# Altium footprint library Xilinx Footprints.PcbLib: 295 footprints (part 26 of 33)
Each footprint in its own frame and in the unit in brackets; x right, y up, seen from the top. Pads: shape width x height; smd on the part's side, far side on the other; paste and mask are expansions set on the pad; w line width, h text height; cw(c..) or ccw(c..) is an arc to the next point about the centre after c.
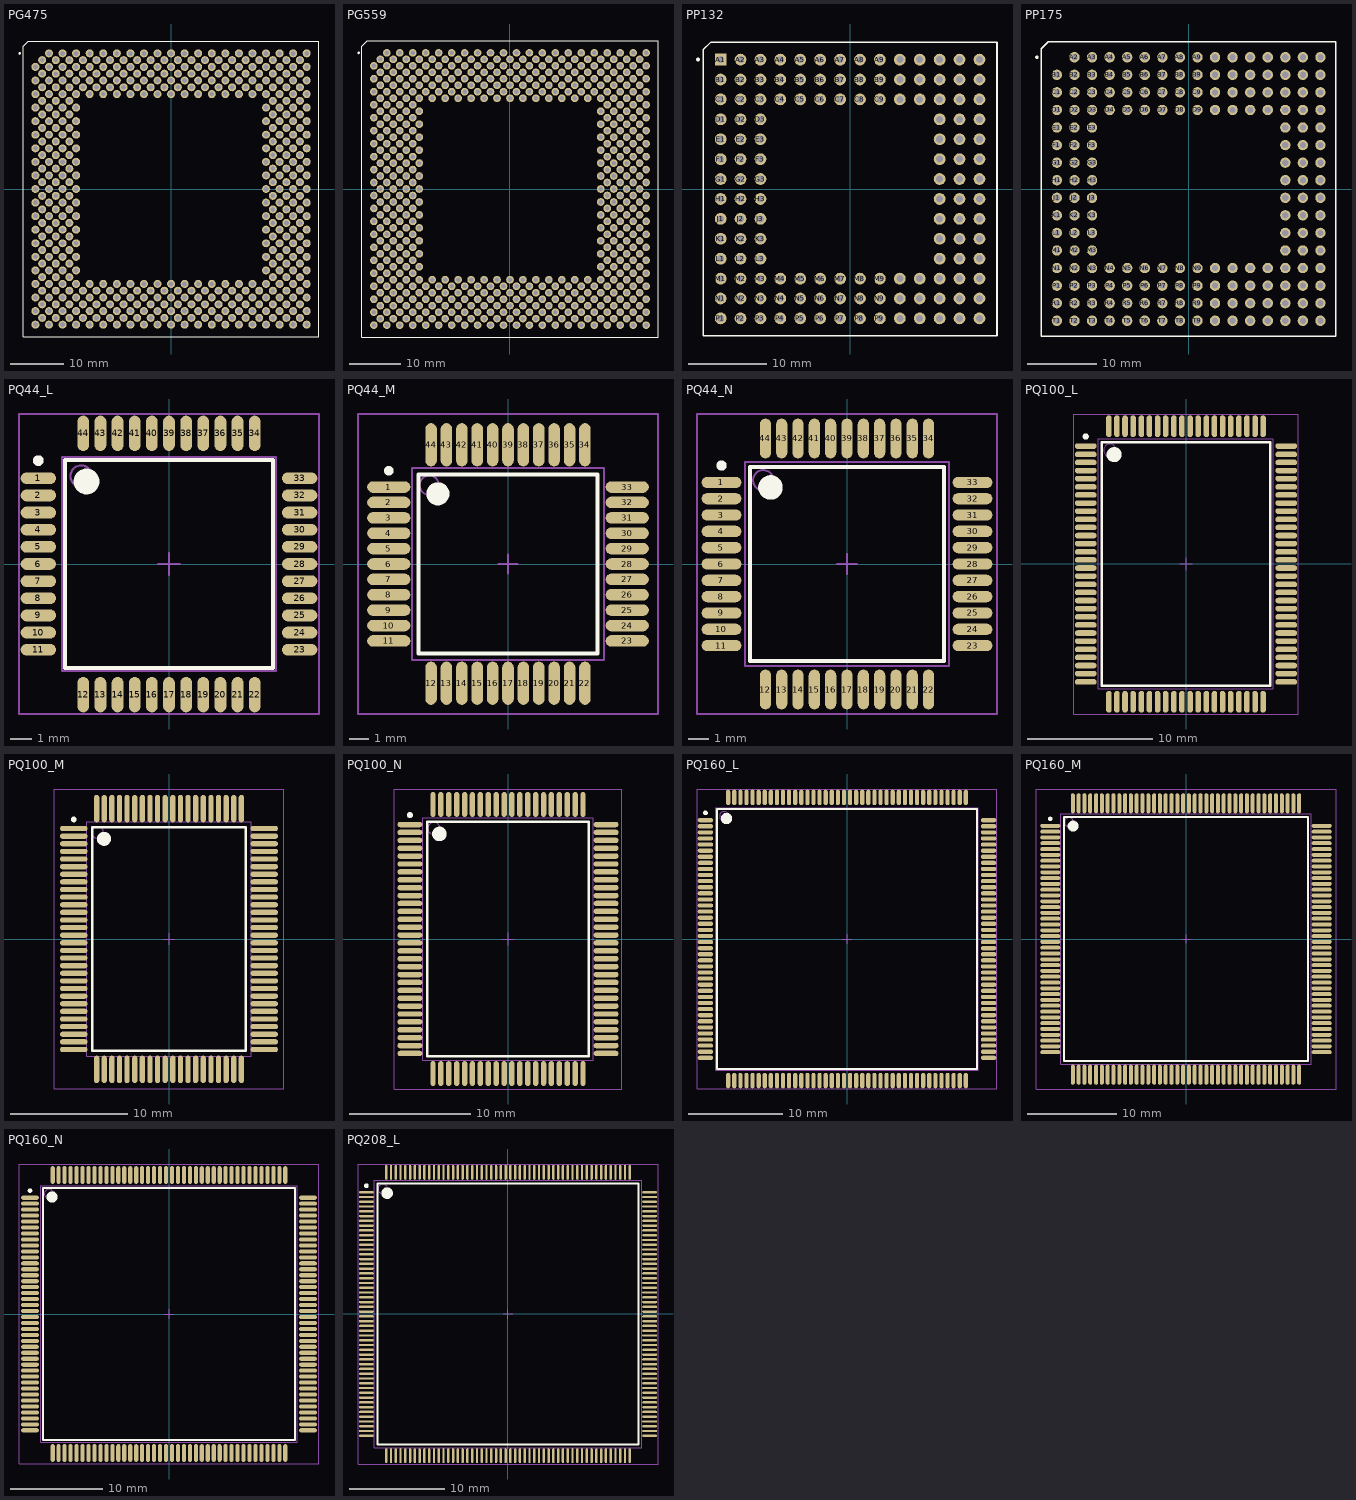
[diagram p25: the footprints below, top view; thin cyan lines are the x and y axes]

## PG475 [mm] "475-Pin Ceramic Pin Grid Array (PG475)"
height 5.86
pads (475):
  round 1.5 hole 0.9: A3(-22.86,25.4) A5(-20.32,25.4) A7(-17.78,25.4) A9(-15.24,25.4) A11(-12.7,25.4) A13(-10.16,25.4) A15(-7.62,25.4) A17(-5.08,25.4) A19(-2.54,25.4) A21(0,25.4) A23(2.54,25.4) A25(5.08,25.4) A27(7.62,25.4) A29(10.16,25.4) A31(12.7,25.4) A33(15.24,25.4) A35(17.78,25.4) A37(20.32,25.4) A39(22.86,25.4) A41(25.4,25.4) AA1(-25.4,0) AA3(-22.86,0) AA5(-20.32,0) AA7(-17.78,0) AA35(17.78,0) AA37(20.32,0) AA39(22.86,0) AA41(25.4,0) AB2(-24.13,-1.27) AB4(-21.59,-1.27) AB6(-19.05,-1.27) AB36(19.05,-1.27) AB38(21.59,-1.27) AB40(24.13,-1.27) AC1(-25.4,-2.54) AC3(-22.86,-2.54) AC5(-20.32,-2.54) AC7(-17.78,-2.54) AC35(17.78,-2.54) AC37(20.32,-2.54) AC39(22.86,-2.54) AC41(25.4,-2.54) AD2(-24.13,-3.81) AD4(-21.59,-3.81) AD6(-19.05,-3.81) AD36(19.05,-3.81) AD38(21.59,-3.81) AD40(24.13,-3.81) AE1(-25.4,-5.08) AE3(-22.86,-5.08) AE5(-20.32,-5.08) AE7(-17.78,-5.08) AE35(17.78,-5.08) AE37(20.32,-5.08) AE39(22.86,-5.08) AE41(25.4,-5.08) AF2(-24.13,-6.35) AF4(-21.59,-6.35) AF6(-19.05,-6.35) AF36(19.05,-6.35) AF38(21.59,-6.35) AF40(24.13,-6.35) AG1(-25.4,-7.62) AG3(-22.86,-7.62) AG5(-20.32,-7.62) AG7(-17.78,-7.62) AG35(17.78,-7.62) AG37(20.32,-7.62) AG39(22.86,-7.62) AG41(25.4,-7.62) AH2(-24.13,-8.89) AH4(-21.59,-8.89) AH6(-19.05,-8.89) AH36(19.05,-8.89) AH38(21.59,-8.89) AH40(24.13,-8.89) AJ1(-25.4,-10.16) AJ3(-22.86,-10.16) AJ5(-20.32,-10.16) AJ7(-17.78,-10.16) AJ35(17.78,-10.16) AJ37(20.32,-10.16) AJ39(22.86,-10.16) AJ41(25.4,-10.16) AK2(-24.13,-11.43) AK4(-21.59,-11.43) AK6(-19.05,-11.43) AK36(19.05,-11.43) AK38(21.59,-11.43) AK40(24.13,-11.43) AL1(-25.4,-12.7) AL3(-22.86,-12.7) AL5(-20.32,-12.7) AL7(-17.78,-12.7) AL35(17.78,-12.7) AL37(20.32,-12.7) AL39(22.86,-12.7) AL41(25.4,-12.7) AM2(-24.13,-13.97) AM4(-21.59,-13.97) AM6(-19.05,-13.97) AM36(19.05,-13.97) AM38(21.59,-13.97) AM40(24.13,-13.97) AN1(-25.4,-15.24) AN3(-22.86,-15.24) AN5(-20.32,-15.24) AN7(-17.78,-15.24) AN35(17.78,-15.24) AN37(20.32,-15.24) AN39(22.86,-15.24) AN41(25.4,-15.24) AP2(-24.13,-16.51) AP4(-21.59,-16.51) AP6(-19.05,-16.51) AP36(19.05,-16.51) AP38(21.59,-16.51) AP40(24.13,-16.51) AR1(-25.4,-17.78) AR3(-22.86,-17.78) AR5(-20.32,-17.78) AR7(-17.78,-17.78) AR9(-15.24,-17.78) AR11(-12.7,-17.78) AR13(-10.16,-17.78) AR15(-7.62,-17.78) AR17(-5.08,-17.78) AR19(-2.54,-17.78) AR21(0,-17.78) AR23(2.54,-17.78) AR25(5.08,-17.78) AR27(7.62,-17.78) AR29(10.16,-17.78) AR31(12.7,-17.78) AR33(15.24,-17.78) AR35(17.78,-17.78) AR37(20.32,-17.78) AR39(22.86,-17.78) AR41(25.4,-17.78) AT2(-24.13,-19.05) AT4(-21.59,-19.05) AT6(-19.05,-19.05) AT8(-16.51,-19.05) AT10(-13.97,-19.05) AT12(-11.43,-19.05) AT14(-8.89,-19.05) AT16(-6.35,-19.05) AT18(-3.81,-19.05) AT20(-1.27,-19.05) AT22(1.27,-19.05) AT24(3.81,-19.05) AT26(6.35,-19.05) AT28(8.89,-19.05) AT30(11.43,-19.05) AT32(13.97,-19.05) AT34(16.51,-19.05) AT36(19.05,-19.05) AT38(21.59,-19.05) AT40(24.13,-19.05) AU1(-25.4,-20.32) AU3(-22.86,-20.32) AU5(-20.32,-20.32) AU7(-17.78,-20.32) AU9(-15.24,-20.32) AU11(-12.7,-20.32) AU13(-10.16,-20.32) AU15(-7.62,-20.32) AU17(-5.08,-20.32) AU19(-2.54,-20.32) AU21(0,-20.32) AU23(2.54,-20.32) AU25(5.08,-20.32) AU27(7.62,-20.32) AU29(10.16,-20.32) AU31(12.7,-20.32) AU33(15.24,-20.32) AU35(17.78,-20.32) AU37(20.32,-20.32) AU39(22.86,-20.32) AU41(25.4,-20.32) AV2(-24.13,-21.59) AV4(-21.59,-21.59) AV6(-19.05,-21.59) AV8(-16.51,-21.59) AV10(-13.97,-21.59) AV12(-11.43,-21.59) AV14(-8.89,-21.59) AV16(-6.35,-21.59) AV18(-3.81,-21.59) AV20(-1.27,-21.59) AV22(1.27,-21.59) AV24(3.81,-21.59) AV26(6.35,-21.59) AV28(8.89,-21.59) AV30(11.43,-21.59) AV32(13.97,-21.59) AV34(16.51,-21.59) AV36(19.05,-21.59) AV38(21.59,-21.59) AV40(24.13,-21.59) AW1(-25.4,-22.86) AW3(-22.86,-22.86) AW5(-20.32,-22.86) AW7(-17.78,-22.86) AW9(-15.24,-22.86) AW11(-12.7,-22.86) AW13(-10.16,-22.86) AW15(-7.62,-22.86) AW17(-5.08,-22.86) AW19(-2.54,-22.86) AW21(0,-22.86) AW23(2.54,-22.86) AW25(5.08,-22.86) AW27(7.62,-22.86) AW29(10.16,-22.86) AW31(12.7,-22.86) AW33(15.24,-22.86) AW35(17.78,-22.86) AW37(20.32,-22.86) AW39(22.86,-22.86) AW41(25.4,-22.86) AY2(-24.13,-24.13) AY4(-21.59,-24.13) AY6(-19.05,-24.13) AY8(-16.51,-24.13) AY10(-13.97,-24.13) AY12(-11.43,-24.13) AY14(-8.89,-24.13) AY16(-6.35,-24.13) AY18(-3.81,-24.13) AY20(-1.27,-24.13) AY22(1.27,-24.13) AY24(3.81,-24.13) AY26(6.35,-24.13) AY28(8.89,-24.13) AY30(11.43,-24.13) AY32(13.97,-24.13) AY34(16.51,-24.13) AY36(19.05,-24.13) AY38(21.59,-24.13) AY40(24.13,-24.13) B2(-24.13,24.13) B4(-21.59,24.13) B6(-19.05,24.13) B8(-16.51,24.13) B10(-13.97,24.13) B12(-11.43,24.13) B14(-8.89,24.13) B16(-6.35,24.13) B18(-3.81,24.13) B20(-1.27,24.13) B22(1.27,24.13) B24(3.81,24.13) B26(6.35,24.13) B28(8.89,24.13) B30(11.43,24.13) B32(13.97,24.13) B34(16.51,24.13) B36(19.05,24.13) B38(21.59,24.13) B40(24.13,24.13) BA1(-25.4,-25.4) BA3(-22.86,-25.4) BA5(-20.32,-25.4) BA7(-17.78,-25.4) BA9(-15.24,-25.4) BA11(-12.7,-25.4) BA13(-10.16,-25.4) BA15(-7.62,-25.4) BA17(-5.08,-25.4) BA19(-2.54,-25.4) BA21(0,-25.4) BA23(2.54,-25.4) BA25(5.08,-25.4) BA27(7.62,-25.4) BA29(10.16,-25.4) BA31(12.7,-25.4) BA33(15.24,-25.4) BA35(17.78,-25.4) BA37(20.32,-25.4) BA39(22.86,-25.4) BA41(25.4,-25.4) C1(-25.4,22.86) C3(-22.86,22.86) C5(-20.32,22.86) C7(-17.78,22.86) C9(-15.24,22.86) C11(-12.7,22.86) C13(-10.16,22.86) C15(-7.62,22.86) C17(-5.08,22.86) C19(-2.54,22.86) C21(0,22.86) C23(2.54,22.86) C25(5.08,22.86) C27(7.62,22.86) C29(10.16,22.86) C31(12.7,22.86) C33(15.24,22.86) C35(17.78,22.86) C37(20.32,22.86) C39(22.86,22.86) C41(25.4,22.86) D2(-24.13,21.59) D4(-21.59,21.59) D6(-19.05,21.59) D8(-16.51,21.59) D10(-13.97,21.59) D12(-11.43,21.59) D14(-8.89,21.59) D16(-6.35,21.59) D18(-3.81,21.59) D20(-1.27,21.59) D22(1.27,21.59) D24(3.81,21.59) D26(6.35,21.59) D28(8.89,21.59) D30(11.43,21.59) D32(13.97,21.59) D34(16.51,21.59) D36(19.05,21.59) D38(21.59,21.59) D40(24.13,21.59) E1(-25.4,20.32) E3(-22.86,20.32) E5(-20.32,20.32) E7(-17.78,20.32) E9(-15.24,20.32) E11(-12.7,20.32) E13(-10.16,20.32) E15(-7.62,20.32) E17(-5.08,20.32) E19(-2.54,20.32) E21(0,20.32) E23(2.54,20.32) E25(5.08,20.32) E27(7.62,20.32) E29(10.16,20.32) E31(12.7,20.32) E33(15.24,20.32) E35(17.78,20.32) E37(20.32,20.32) E39(22.86,20.32) E41(25.4,20.32) F2(-24.13,19.05) F4(-21.59,19.05) F6(-19.05,19.05) F8(-16.51,19.05) F10(-13.97,19.05) F12(-11.43,19.05) F14(-8.89,19.05) F16(-6.35,19.05) F18(-3.81,19.05) F20(-1.27,19.05) F22(1.27,19.05) F24(3.81,19.05) F26(6.35,19.05) F28(8.89,19.05) F30(11.43,19.05) F32(13.97,19.05) F34(16.51,19.05) F36(19.05,19.05) F38(21.59,19.05) F40(24.13,19.05) G1(-25.4,17.78) G3(-22.86,17.78) G5(-20.32,17.78) G7(-17.78,17.78) G9(-15.24,17.78) G11(-12.7,17.78) G13(-10.16,17.78) G15(-7.62,17.78) G17(-5.08,17.78) G19(-2.54,17.78) G21(0,17.78) G23(2.54,17.78) G25(5.08,17.78) G27(7.62,17.78) G29(10.16,17.78) G31(12.7,17.78) G33(15.24,17.78) G35(17.78,17.78) G37(20.32,17.78) G39(22.86,17.78) G41(25.4,17.78) H2(-24.13,16.51) H4(-21.59,16.51) H6(-19.05,16.51) H36(19.05,16.51) H38(21.59,16.51) H40(24.13,16.51) J1(-25.4,15.24) J3(-22.86,15.24) J5(-20.32,15.24) J7(-17.78,15.24) J35(17.78,15.24) J37(20.32,15.24) J39(22.86,15.24) J41(25.4,15.24) K2(-24.13,13.97) K4(-21.59,13.97) K6(-19.05,13.97) K36(19.05,13.97) K38(21.59,13.97) K40(24.13,13.97) L1(-25.4,12.7) L3(-22.86,12.7) L5(-20.32,12.7) L7(-17.78,12.7) L35(17.78,12.7) L37(20.32,12.7) L39(22.86,12.7) L41(25.4,12.7) M2(-24.13,11.43) M4(-21.59,11.43) M6(-19.05,11.43) M36(19.05,11.43) M38(21.59,11.43) M40(24.13,11.43) N1(-25.4,10.16) N3(-22.86,10.16) N5(-20.32,10.16) N7(-17.78,10.16) N35(17.78,10.16) N37(20.32,10.16) N39(22.86,10.16) N41(25.4,10.16) P2(-24.13,8.89) P4(-21.59,8.89) P6(-19.05,8.89) P36(19.05,8.89) P38(21.59,8.89) P40(24.13,8.89) R1(-25.4,7.62) R3(-22.86,7.62) R5(-20.32,7.62) R7(-17.78,7.62) R35(17.78,7.62) R37(20.32,7.62) R39(22.86,7.62) R41(25.4,7.62) T2(-24.13,6.35) T4(-21.59,6.35) T6(-19.05,6.35) T36(19.05,6.35) T38(21.59,6.35) T40(24.13,6.35) U1(-25.4,5.08) U3(-22.86,5.08) U5(-20.32,5.08) U7(-17.78,5.08) U35(17.78,5.08) U37(20.32,5.08) U39(22.86,5.08) U41(25.4,5.08) V2(-24.13,3.81) V4(-21.59,3.81) V6(-19.05,3.81) V36(19.05,3.81) V38(21.59,3.81) V40(24.13,3.81) W1(-25.4,2.54) W3(-22.86,2.54) W5(-20.32,2.54) W7(-17.78,2.54) W35(17.78,2.54) W37(20.32,2.54) W39(22.86,2.54) W41(25.4,2.54) Y2(-24.13,1.27) Y4(-21.59,1.27) Y6(-19.05,1.27) Y36(19.05,1.27) Y38(21.59,1.27) Y40(24.13,1.27)
Top Overlay:
  circle w0.25: c-28.35,25.4 r0.125
  lines w0.2: -27.7,-27.7 27.7,-27.7 27.7,27.7 -26.7,27.7 -27.7,26.7 -27.7,-27.7

## PG559 [mm] "559-Pin Ceramic Pin Grid Array (PG559)"
height 5.86
pads (559):
  round 1.5 hole 0.9: A3(-24.13,26.67) A5(-21.59,26.67) A7(-19.05,26.67) A9(-16.51,26.67) A11(-13.97,26.67) A13(-11.43,26.67) A15(-8.89,26.67) A17(-6.35,26.67) A19(-3.81,26.67) A21(-1.27,26.67) A23(1.27,26.67) A25(3.81,26.67) A27(6.35,26.67) A29(8.89,26.67) A31(11.43,26.67) A33(13.97,26.67) A35(16.51,26.67) A37(19.05,26.67) A39(21.59,26.67) A41(24.13,26.67) A43(26.67,26.67) AA1(-26.67,1.27) AA3(-24.13,1.27) AA5(-21.59,1.27) AA7(-19.05,1.27) AA37(19.05,1.27) AA39(21.59,1.27) AA41(24.13,1.27) AA43(26.67,1.27) AB2(-25.4,0) AB4(-22.86,0) AB6(-20.32,0) AB8(-17.78,0) AB36(17.78,0) AB38(20.32,0) AB40(22.86,0) AB42(25.4,0) AC1(-26.67,-1.27) AC3(-24.13,-1.27) AC5(-21.59,-1.27) AC7(-19.05,-1.27) AC37(19.05,-1.27) AC39(21.59,-1.27) AC41(24.13,-1.27) AC43(26.67,-1.27) AD2(-25.4,-2.54) AD4(-22.86,-2.54) AD6(-20.32,-2.54) AD8(-17.78,-2.54) AD36(17.78,-2.54) AD38(20.32,-2.54) AD40(22.86,-2.54) AD42(25.4,-2.54) AE1(-26.67,-3.81) AE3(-24.13,-3.81) AE5(-21.59,-3.81) AE7(-19.05,-3.81) AE37(19.05,-3.81) AE39(21.59,-3.81) AE41(24.13,-3.81) AE43(26.67,-3.81) AF2(-25.4,-5.08) AF4(-22.86,-5.08) AF6(-20.32,-5.08) AF8(-17.78,-5.08) AF36(17.78,-5.08) AF38(20.32,-5.08) AF40(22.86,-5.08) AF42(25.4,-5.08) AG1(-26.67,-6.35) AG3(-24.13,-6.35) AG5(-21.59,-6.35) AG7(-19.05,-6.35) AG37(19.05,-6.35) AG39(21.59,-6.35) AG41(24.13,-6.35) AG43(26.67,-6.35) AH2(-25.4,-7.62) AH4(-22.86,-7.62) AH6(-20.32,-7.62) AH8(-17.78,-7.62) AH36(17.78,-7.62) AH38(20.32,-7.62) AH40(22.86,-7.62) AH42(25.4,-7.62) AJ1(-26.67,-8.89) AJ3(-24.13,-8.89) AJ5(-21.59,-8.89) AJ7(-19.05,-8.89) AJ37(19.05,-8.89) AJ39(21.59,-8.89) AJ41(24.13,-8.89) AJ43(26.67,-8.89) AK2(-25.4,-10.16) AK4(-22.86,-10.16) AK6(-20.32,-10.16) AK8(-17.78,-10.16) AK36(17.78,-10.16) AK38(20.32,-10.16) AK40(22.86,-10.16) AK42(25.4,-10.16) AL1(-26.67,-11.43) AL3(-24.13,-11.43) AL5(-21.59,-11.43) AL7(-19.05,-11.43) AL37(19.05,-11.43) AL39(21.59,-11.43) AL41(24.13,-11.43) AL43(26.67,-11.43) AM2(-25.4,-12.7) AM4(-22.86,-12.7) AM6(-20.32,-12.7) AM8(-17.78,-12.7) AM36(17.78,-12.7) AM38(20.32,-12.7) AM40(22.86,-12.7) AM42(25.4,-12.7) AN1(-26.67,-13.97) AN3(-24.13,-13.97) AN5(-21.59,-13.97) AN7(-19.05,-13.97) AN37(19.05,-13.97) AN39(21.59,-13.97) AN41(24.13,-13.97) AN43(26.67,-13.97) AP2(-25.4,-15.24) AP4(-22.86,-15.24) AP6(-20.32,-15.24) AP8(-17.78,-15.24) AP36(17.78,-15.24) AP38(20.32,-15.24) AP40(22.86,-15.24) AP42(25.4,-15.24) AR1(-26.67,-16.51) AR3(-24.13,-16.51) AR5(-21.59,-16.51) AR7(-19.05,-16.51) AR37(19.05,-16.51) AR39(21.59,-16.51) AR41(24.13,-16.51) AR43(26.67,-16.51) AT2(-25.4,-17.78) AT4(-22.86,-17.78) AT6(-20.32,-17.78) AT8(-17.78,-17.78) AT10(-15.24,-17.78) AT12(-12.7,-17.78) AT14(-10.16,-17.78) AT16(-7.62,-17.78) AT18(-5.08,-17.78) AT20(-2.54,-17.78) AT22(0,-17.78) AT24(2.54,-17.78) AT26(5.08,-17.78) AT28(7.62,-17.78) AT30(10.16,-17.78) AT32(12.7,-17.78) AT34(15.24,-17.78) AT36(17.78,-17.78) AT38(20.32,-17.78) AT40(22.86,-17.78) AT42(25.4,-17.78) AU1(-26.67,-19.05) AU3(-24.13,-19.05) AU5(-21.59,-19.05) AU7(-19.05,-19.05) AU9(-16.51,-19.05) AU11(-13.97,-19.05) AU13(-11.43,-19.05) AU15(-8.89,-19.05) AU17(-6.35,-19.05) AU19(-3.81,-19.05) AU21(-1.27,-19.05) AU23(1.27,-19.05) AU25(3.81,-19.05) AU27(6.35,-19.05) AU29(8.89,-19.05) AU31(11.43,-19.05) AU33(13.97,-19.05) AU35(16.51,-19.05) AU37(19.05,-19.05) AU39(21.59,-19.05) AU41(24.13,-19.05) AU43(26.67,-19.05) AV2(-25.4,-20.32) AV4(-22.86,-20.32) AV6(-20.32,-20.32) AV8(-17.78,-20.32) AV10(-15.24,-20.32) AV12(-12.7,-20.32) AV14(-10.16,-20.32) AV16(-7.62,-20.32) AV18(-5.08,-20.32) AV20(-2.54,-20.32) AV22(0,-20.32) AV24(2.54,-20.32) AV26(5.08,-20.32) AV28(7.62,-20.32) AV30(10.16,-20.32) AV32(12.7,-20.32) AV34(15.24,-20.32) AV36(17.78,-20.32) AV38(20.32,-20.32) AV40(22.86,-20.32) AV42(25.4,-20.32) AW1(-26.67,-21.59) AW3(-24.13,-21.59) AW5(-21.59,-21.59) AW7(-19.05,-21.59) AW9(-16.51,-21.59) AW11(-13.97,-21.59) AW13(-11.43,-21.59) AW15(-8.89,-21.59) AW17(-6.35,-21.59) AW19(-3.81,-21.59) AW21(-1.27,-21.59) AW23(1.27,-21.59) AW25(3.81,-21.59) AW27(6.35,-21.59) AW29(8.89,-21.59) AW31(11.43,-21.59) AW33(13.97,-21.59) AW35(16.51,-21.59) AW37(19.05,-21.59) AW39(21.59,-21.59) AW41(24.13,-21.59) AW43(26.67,-21.59) AY2(-25.4,-22.86) AY4(-22.86,-22.86) AY6(-20.32,-22.86) AY8(-17.78,-22.86) AY10(-15.24,-22.86) AY12(-12.7,-22.86) AY14(-10.16,-22.86) AY16(-7.62,-22.86) AY18(-5.08,-22.86) AY20(-2.54,-22.86) AY22(0,-22.86) AY24(2.54,-22.86) AY26(5.08,-22.86) AY28(7.62,-22.86) AY30(10.16,-22.86) AY32(12.7,-22.86) AY34(15.24,-22.86) AY36(17.78,-22.86) AY38(20.32,-22.86) AY40(22.86,-22.86) AY42(25.4,-22.86) B2(-25.4,25.4) B4(-22.86,25.4) B6(-20.32,25.4) B8(-17.78,25.4) B10(-15.24,25.4) B12(-12.7,25.4) B14(-10.16,25.4) B16(-7.62,25.4) B18(-5.08,25.4) B20(-2.54,25.4) B22(0,25.4) B24(2.54,25.4) B26(5.08,25.4) B28(7.62,25.4) B30(10.16,25.4) B32(12.7,25.4) B34(15.24,25.4) B36(17.78,25.4) B38(20.32,25.4) B40(22.86,25.4) B42(25.4,25.4) BA1(-26.67,-24.13) BA3(-24.13,-24.13) BA5(-21.59,-24.13) BA7(-19.05,-24.13) BA9(-16.51,-24.13) BA11(-13.97,-24.13) BA13(-11.43,-24.13) BA15(-8.89,-24.13) BA17(-6.35,-24.13) BA19(-3.81,-24.13) BA21(-1.27,-24.13) BA23(1.27,-24.13) BA25(3.81,-24.13) BA27(6.35,-24.13) BA29(8.89,-24.13) BA31(11.43,-24.13) BA33(13.97,-24.13) BA35(16.51,-24.13) BA37(19.05,-24.13) BA39(21.59,-24.13) BA41(24.13,-24.13) BA43(26.67,-24.13) BB2(-25.4,-25.4) BB4(-22.86,-25.4) BB6(-20.32,-25.4) BB8(-17.78,-25.4) BB10(-15.24,-25.4) BB12(-12.7,-25.4) BB14(-10.16,-25.4) BB16(-7.62,-25.4) BB18(-5.08,-25.4) BB20(-2.54,-25.4) BB22(0,-25.4) BB24(2.54,-25.4) BB26(5.08,-25.4) BB28(7.62,-25.4) BB30(10.16,-25.4) BB32(12.7,-25.4) BB34(15.24,-25.4) BB36(17.78,-25.4) BB38(20.32,-25.4) BB40(22.86,-25.4) BB42(25.4,-25.4) BC1(-26.67,-26.67) BC3(-24.13,-26.67) BC5(-21.59,-26.67) BC7(-19.05,-26.67) BC9(-16.51,-26.67) BC11(-13.97,-26.67) BC13(-11.43,-26.67) BC15(-8.89,-26.67) BC17(-6.35,-26.67) BC19(-3.81,-26.67) BC21(-1.27,-26.67) BC23(1.27,-26.67) BC25(3.81,-26.67) BC27(6.35,-26.67) BC29(8.89,-26.67) BC31(11.43,-26.67) BC33(13.97,-26.67) BC35(16.51,-26.67) BC37(19.05,-26.67) BC39(21.59,-26.67) BC41(24.13,-26.67) BC43(26.67,-26.67) C1(-26.67,24.13) C3(-24.13,24.13) C5(-21.59,24.13) C7(-19.05,24.13) C9(-16.51,24.13) C11(-13.97,24.13) C13(-11.43,24.13) C15(-8.89,24.13) C17(-6.35,24.13) C19(-3.81,24.13) C21(-1.27,24.13) C23(1.27,24.13) C25(3.81,24.13) C27(6.35,24.13) C29(8.89,24.13) C31(11.43,24.13) C33(13.97,24.13) C35(16.51,24.13) C37(19.05,24.13) C39(21.59,24.13) C41(24.13,24.13) C43(26.67,24.13) D2(-25.4,22.86) D4(-22.86,22.86) D6(-20.32,22.86) D8(-17.78,22.86) D10(-15.24,22.86) D12(-12.7,22.86) D14(-10.16,22.86) D16(-7.62,22.86) D18(-5.08,22.86) D20(-2.54,22.86) D22(0,22.86) D24(2.54,22.86) D26(5.08,22.86) D28(7.62,22.86) D30(10.16,22.86) D32(12.7,22.86) D34(15.24,22.86) D36(17.78,22.86) D38(20.32,22.86) D40(22.86,22.86) D42(25.4,22.86) E1(-26.67,21.59) E3(-24.13,21.59) E5(-21.59,21.59) E7(-19.05,21.59) E9(-16.51,21.59) E11(-13.97,21.59) E13(-11.43,21.59) E15(-8.89,21.59) E17(-6.35,21.59) E19(-3.81,21.59) E21(-1.27,21.59) E23(1.27,21.59) E25(3.81,21.59) E27(6.35,21.59) E29(8.89,21.59) E31(11.43,21.59) E33(13.97,21.59) E35(16.51,21.59) E37(19.05,21.59) E39(21.59,21.59) E41(24.13,21.59) E43(26.67,21.59) F2(-25.4,20.32) F4(-22.86,20.32) F6(-20.32,20.32) F8(-17.78,20.32) F10(-15.24,20.32) F12(-12.7,20.32) F14(-10.16,20.32) F16(-7.62,20.32) F18(-5.08,20.32) F20(-2.54,20.32) F22(0,20.32) F24(2.54,20.32) F26(5.08,20.32) F28(7.62,20.32) F30(10.16,20.32) F32(12.7,20.32) F34(15.24,20.32) F36(17.78,20.32) F38(20.32,20.32) F40(22.86,20.32) F42(25.4,20.32) G1(-26.67,19.05) G3(-24.13,19.05) G5(-21.59,19.05) G7(-19.05,19.05) G9(-16.51,19.05) G11(-13.97,19.05) G13(-11.43,19.05) G15(-8.89,19.05) G17(-6.35,19.05) G19(-3.81,19.05) G21(-1.27,19.05) G23(1.27,19.05) G25(3.81,19.05) G27(6.35,19.05) G29(8.89,19.05) G31(11.43,19.05) G33(13.97,19.05) G35(16.51,19.05) G37(19.05,19.05) G39(21.59,19.05) G41(24.13,19.05) G43(26.67,19.05) H2(-25.4,17.78) H4(-22.86,17.78) H6(-20.32,17.78) H8(-17.78,17.78) H10(-15.24,17.78) H12(-12.7,17.78) H14(-10.16,17.78) H16(-7.62,17.78) H18(-5.08,17.78) H20(-2.54,17.78) H22(0,17.78) H24(2.54,17.78) H26(5.08,17.78) H28(7.62,17.78) H30(10.16,17.78) H32(12.7,17.78) H34(15.24,17.78) H36(17.78,17.78) H38(20.32,17.78) H40(22.86,17.78) H42(25.4,17.78) J1(-26.67,16.51) J3(-24.13,16.51) J5(-21.59,16.51) J7(-19.05,16.51) J37(19.05,16.51) J39(21.59,16.51) J41(24.13,16.51) J43(26.67,16.51) K2(-25.4,15.24) K4(-22.86,15.24) K6(-20.32,15.24) K8(-17.78,15.24) K36(17.78,15.24) K38(20.32,15.24) K40(22.86,15.24) K42(25.4,15.24) L1(-26.67,13.97) L3(-24.13,13.97) L5(-21.59,13.97) L7(-19.05,13.97) L37(19.05,13.97) L39(21.59,13.97) L41(24.13,13.97) L43(26.67,13.97) M2(-25.4,12.7) M4(-22.86,12.7) M6(-20.32,12.7) M8(-17.78,12.7) M36(17.78,12.7) M38(20.32,12.7) M40(22.86,12.7) M42(25.4,12.7) N1(-26.67,11.43) N3(-24.13,11.43) N5(-21.59,11.43) N7(-19.05,11.43) N37(19.05,11.43) N39(21.59,11.43) N41(24.13,11.43) N43(26.67,11.43) P2(-25.4,10.16) P4(-22.86,10.16) P6(-20.32,10.16) P8(-17.78,10.16) P36(17.78,10.16) P38(20.32,10.16) P40(22.86,10.16) P42(25.4,10.16) R1(-26.67,8.89) R3(-24.13,8.89) R5(-21.59,8.89) R7(-19.05,8.89) R37(19.05,8.89) R39(21.59,8.89) R41(24.13,8.89) R43(26.67,8.89) T2(-25.4,7.62) T4(-22.86,7.62) T6(-20.32,7.62) T8(-17.78,7.62) T36(17.78,7.62) T38(20.32,7.62) T40(22.86,7.62) T42(25.4,7.62) U1(-26.67,6.35) U3(-24.13,6.35) U5(-21.59,6.35) U7(-19.05,6.35) U37(19.05,6.35) U39(21.59,6.35) U41(24.13,6.35) U43(26.67,6.35) V2(-25.4,5.08) V4(-22.86,5.08) V6(-20.32,5.08) V8(-17.78,5.08) V36(17.78,5.08) V38(20.32,5.08) V40(22.86,5.08) V42(25.4,5.08) W1(-26.67,3.81) W3(-24.13,3.81) W5(-21.59,3.81) W7(-19.05,3.81) W37(19.05,3.81) W39(21.59,3.81) W41(24.13,3.81) W43(26.67,3.81) Y2(-25.4,2.54) Y4(-22.86,2.54) Y6(-20.32,2.54) Y8(-17.78,2.54) Y36(17.78,2.54) Y38(20.32,2.54) Y40(22.86,2.54) Y42(25.4,2.54)
Top Overlay:
  circle w0.25: c-29.65,26.67 r0.125
  lines w0.2: -29,-29 -29,28 -28,29 29,29 29,-29 -29,-29

## PP132 [mm] "132-Pin Plastic Pin Grid Array (PP132)"
height 4.191
pads (132):
  rect 1.5x1.5 hole 0.9: A1(-16.51,16.51)
  round 1.5 hole 0.9: A2(-13.97,16.51) A3(-11.43,16.51) A4(-8.89,16.51) A5(-6.35,16.51) A6(-3.81,16.51) A7(-1.27,16.51) A8(1.27,16.51) A9(3.81,16.51) A10(6.35,16.51) A11(8.89,16.51) A12(11.43,16.51) A13(13.97,16.51) A14(16.51,16.51) B1(-16.51,13.97) B2(-13.97,13.97) B3(-11.43,13.97) B4(-8.89,13.97) B5(-6.35,13.97) B6(-3.81,13.97) B7(-1.27,13.97) B8(1.27,13.97) B9(3.81,13.97) B10(6.35,13.97) B11(8.89,13.97) B12(11.43,13.97) B13(13.97,13.97) B14(16.51,13.97) C1(-16.51,11.43) C2(-13.97,11.43) C3(-11.43,11.43) C4(-8.89,11.43) C5(-6.35,11.43) C6(-3.81,11.43) C7(-1.27,11.43) C8(1.27,11.43) C9(3.81,11.43) C10(6.35,11.43) C11(8.89,11.43) C12(11.43,11.43) C13(13.97,11.43) C14(16.51,11.43) D1(-16.51,8.89) D2(-13.97,8.89) D3(-11.43,8.89) D12(11.43,8.89) D13(13.97,8.89) D14(16.51,8.89) E1(-16.51,6.35) E2(-13.97,6.35) E3(-11.43,6.35) E12(11.43,6.35) E13(13.97,6.35) E14(16.51,6.35) F1(-16.51,3.81) F2(-13.97,3.81) F3(-11.43,3.81) F12(11.43,3.81) F13(13.97,3.81) F14(16.51,3.81) G1(-16.51,1.27) G2(-13.97,1.27) G3(-11.43,1.27) G12(11.43,1.27) G13(13.97,1.27) G14(16.51,1.27) H1(-16.51,-1.27) H2(-13.97,-1.27) H3(-11.43,-1.27) H12(11.43,-1.27) H13(13.97,-1.27) H14(16.51,-1.27) J1(-16.51,-3.81) J2(-13.97,-3.81) J3(-11.43,-3.81) J12(11.43,-3.81) J13(13.97,-3.81) J14(16.51,-3.81) K1(-16.51,-6.35) K2(-13.97,-6.35) K3(-11.43,-6.35) K12(11.43,-6.35) K13(13.97,-6.35) K14(16.51,-6.35) L1(-16.51,-8.89) L2(-13.97,-8.89) L3(-11.43,-8.89) L12(11.43,-8.89) L13(13.97,-8.89) L14(16.51,-8.89) M1(-16.51,-11.43) M2(-13.97,-11.43) M3(-11.43,-11.43) M4(-8.89,-11.43) M5(-6.35,-11.43) M6(-3.81,-11.43) M7(-1.27,-11.43) M8(1.27,-11.43) M9(3.81,-11.43) M10(6.35,-11.43) M11(8.89,-11.43) M12(11.43,-11.43) M13(13.97,-11.43) M14(16.51,-11.43) N1(-16.51,-13.97) N2(-13.97,-13.97) N3(-11.43,-13.97) N4(-8.89,-13.97) N5(-6.35,-13.97) N6(-3.81,-13.97) N7(-1.27,-13.97) N8(1.27,-13.97) N9(3.81,-13.97) N10(6.35,-13.97) N11(8.89,-13.97) N12(11.43,-13.97) N13(13.97,-13.97) N14(16.51,-13.97) P1(-16.51,-16.51) P2(-13.97,-16.51) P3(-11.43,-16.51) P4(-8.89,-16.51) P5(-6.35,-16.51) P6(-3.81,-16.51) P7(-1.27,-16.51) P8(1.27,-16.51) P9(3.81,-16.51) P10(6.35,-16.51) P11(8.89,-16.51) P12(11.43,-16.51) P13(13.97,-16.51) P14(16.51,-16.51)
Top Overlay:
  circle w0.25: c-19.4,16.51 r0.125
  lines w0.2: -18.75,-18.75 -18.75,17.75 -17.75,18.75 18.75,18.75 18.75,-18.75 -18.75,-18.75

## PP175 [mm] "175-Pin Plastic Pin Grid Array (PP175)"
height 4.191
pads (175):
  round 1.5 hole 0.9: A2(-16.51,19.05) A3(-13.97,19.05) A4(-11.43,19.05) A5(-8.89,19.05) A6(-6.35,19.05) A7(-3.81,19.05) A8(-1.27,19.05) A9(1.27,19.05) A10(3.81,19.05) A11(6.35,19.05) A12(8.89,19.05) A13(11.43,19.05) A14(13.97,19.05) A15(16.51,19.05) A16(19.05,19.05) B1(-19.05,16.51) B2(-16.51,16.51) B3(-13.97,16.51) B4(-11.43,16.51) B5(-8.89,16.51) B6(-6.35,16.51) B7(-3.81,16.51) B8(-1.27,16.51) B9(1.27,16.51) B10(3.81,16.51) B11(6.35,16.51) B12(8.89,16.51) B13(11.43,16.51) B14(13.97,16.51) B15(16.51,16.51) B16(19.05,16.51) C1(-19.05,13.97) C2(-16.51,13.97) C3(-13.97,13.97) C4(-11.43,13.97) C5(-8.89,13.97) C6(-6.35,13.97) C7(-3.81,13.97) C8(-1.27,13.97) C9(1.27,13.97) C10(3.81,13.97) C11(6.35,13.97) C12(8.89,13.97) C13(11.43,13.97) C14(13.97,13.97) C15(16.51,13.97) C16(19.05,13.97) D1(-19.05,11.43) D2(-16.51,11.43) D3(-13.97,11.43) D4(-11.43,11.43) D5(-8.89,11.43) D6(-6.35,11.43) D7(-3.81,11.43) D8(-1.27,11.43) D9(1.27,11.43) D10(3.81,11.43) D11(6.35,11.43) D12(8.89,11.43) D13(11.43,11.43) D14(13.97,11.43) D15(16.51,11.43) D16(19.05,11.43) E1(-19.05,8.89) E2(-16.51,8.89) E3(-13.97,8.89) E14(13.97,8.89) E15(16.51,8.89) E16(19.05,8.89) F1(-19.05,6.35) F2(-16.51,6.35) F3(-13.97,6.35) F14(13.97,6.35) F15(16.51,6.35) F16(19.05,6.35) G1(-19.05,3.81) G2(-16.51,3.81) G3(-13.97,3.81) G14(13.97,3.81) G15(16.51,3.81) G16(19.05,3.81) H1(-19.05,1.27) H2(-16.51,1.27) H3(-13.97,1.27) H14(13.97,1.27) H15(16.51,1.27) H16(19.05,1.27) J1(-19.05,-1.27) J2(-16.51,-1.27) J3(-13.97,-1.27) J14(13.97,-1.27) J15(16.51,-1.27) J16(19.05,-1.27) K1(-19.05,-3.81) K2(-16.51,-3.81) K3(-13.97,-3.81) K14(13.97,-3.81) K15(16.51,-3.81) K16(19.05,-3.81) L1(-19.05,-6.35) L2(-16.51,-6.35) L3(-13.97,-6.35) L14(13.97,-6.35) L15(16.51,-6.35) L16(19.05,-6.35) M1(-19.05,-8.89) M2(-16.51,-8.89) M3(-13.97,-8.89) M14(13.97,-8.89) M15(16.51,-8.89) M16(19.05,-8.89) N1(-19.05,-11.43) N2(-16.51,-11.43) N3(-13.97,-11.43) N4(-11.43,-11.43) N5(-8.89,-11.43) N6(-6.35,-11.43) N7(-3.81,-11.43) N8(-1.27,-11.43) N9(1.27,-11.43) N10(3.81,-11.43) N11(6.35,-11.43) N12(8.89,-11.43) N13(11.43,-11.43) N14(13.97,-11.43) N15(16.51,-11.43) N16(19.05,-11.43) P1(-19.05,-13.97) P2(-16.51,-13.97) P3(-13.97,-13.97) P4(-11.43,-13.97) P5(-8.89,-13.97) P6(-6.35,-13.97) P7(-3.81,-13.97) P8(-1.27,-13.97) P9(1.27,-13.97) P10(3.81,-13.97) P11(6.35,-13.97) P12(8.89,-13.97) P13(11.43,-13.97) P14(13.97,-13.97) P15(16.51,-13.97) P16(19.05,-13.97) R1(-19.05,-16.51) R2(-16.51,-16.51) R3(-13.97,-16.51) R4(-11.43,-16.51) R5(-8.89,-16.51) R6(-6.35,-16.51) R7(-3.81,-16.51) R8(-1.27,-16.51) R9(1.27,-16.51) R10(3.81,-16.51) R11(6.35,-16.51) R12(8.89,-16.51) R13(11.43,-16.51) R14(13.97,-16.51) R15(16.51,-16.51) R16(19.05,-16.51) T1(-19.05,-19.05) T2(-16.51,-19.05) T3(-13.97,-19.05) T4(-11.43,-19.05) T5(-8.89,-19.05) T6(-6.35,-19.05) T7(-3.81,-19.05) T8(-1.27,-19.05) T9(1.27,-19.05) T10(3.81,-19.05) T11(6.35,-19.05) T12(8.89,-19.05) T13(11.43,-19.05) T14(13.97,-19.05) T15(16.51,-19.05) T16(19.05,-19.05)
Top Overlay:
  circle w0.25: c-21.95,19.05 r0.125
  lines w0.2: -21.3,-21.3 21.3,-21.3 21.3,21.3 -20.3,21.3 -21.3,20.3 -21.3,-21.3

## PQ44_L [mm] "44-Pin Plastic Quad Flat Pack (PQ44), IPC High Density"
height 2.35
pads (44):
  oval 1.65x0.55 smd: 1(-6.1,4) 2(-6.1,3.2) 3(-6.1,2.4) 4(-6.1,1.6) 5(-6.1,0.8) 6(-6.1,0) 7(-6.1,-0.8) 8(-6.1,-1.6) 9(-6.1,-2.4) 10(-6.1,-3.2) 11(-6.1,-4) 23(6.1,-4) 24(6.1,-3.2) 25(6.1,-2.4) 26(6.1,-1.6) 27(6.1,-0.8) 28(6.1,0) 29(6.1,0.8) 30(6.1,1.6) 31(6.1,2.4) 32(6.1,3.2) 33(6.1,4)
  oval 0.55x1.65 smd: 12(-4,-6.1) 13(-3.2,-6.1) 14(-2.4,-6.1) 15(-1.6,-6.1) 16(-0.8,-6.1) 17(0,-6.1) 18(0.8,-6.1) 19(1.6,-6.1) 20(2.4,-6.1) 21(3.2,-6.1) 22(4,-6.1) 34(4,6.1) 35(3.2,6.1) 36(2.4,6.1) 37(1.6,6.1) 38(0.8,6.1) 39(0,6.1) 40(-0.8,6.1) 41(-1.6,6.1) 42(-2.4,6.1) 43(-3.2,6.1) 44(-4,6.1)
Top Overlay:
  circle w0.6: c-3.85,3.85 r0.3
  circle w0.25: c-6.1,4.825 r0.125
  lines w0.2: -4.85,-4.85 4.85,-4.85 4.85,4.85 -4.85,4.85 -4.85,-4.85
Mechanical 13:
  circle w0.1: c-4.1,4.1 r0.5
  lines w0.1: -5,-5 5,-5 5,5 -5,5 -5,-5
Mechanical 15:
  lines w0.1: -0.5,0 0.5,0 ; 0,-0.5 0,0.5 ; -7,-7 7,-7 7,7 -7,7 -7,-7
3D body: height 2.35, standoff 0, extent -5,-5 5,5

## PQ44_M [mm] "44-Pin Plastic Quad Flat Pack (PQ44), IPC Low Density"
height 2.35
pads (44):
  oval 2.25x0.6 smd: 1(-6.2,4) 2(-6.2,3.2) 3(-6.2,2.4) 4(-6.2,1.6) 5(-6.2,0.8) 6(-6.2,0) 7(-6.2,-0.8) 8(-6.2,-1.6) 9(-6.2,-2.4) 10(-6.2,-3.2) 11(-6.2,-4) 23(6.2,-4) 24(6.2,-3.2) 25(6.2,-2.4) 26(6.2,-1.6) 27(6.2,-0.8) 28(6.2,0) 29(6.2,0.8) 30(6.2,1.6) 31(6.2,2.4) 32(6.2,3.2) 33(6.2,4)
  oval 0.6x2.25 smd: 12(-4,-6.2) 13(-3.2,-6.2) 14(-2.4,-6.2) 15(-1.6,-6.2) 16(-0.8,-6.2) 17(0,-6.2) 18(0.8,-6.2) 19(1.6,-6.2) 20(2.4,-6.2) 21(3.2,-6.2) 22(4,-6.2) 34(4,6.2) 35(3.2,6.2) 36(2.4,6.2) 37(1.6,6.2) 38(0.8,6.2) 39(0,6.2) 40(-0.8,6.2) 41(-1.6,6.2) 42(-2.4,6.2) 43(-3.2,6.2) 44(-4,6.2)
Top Overlay:
  circle w0.25: c-6.2,4.85 r0.125
  circle w0.6: c-3.65,3.65 r0.3
  lines w0.2: -4.65,-4.65 -4.65,4.65 4.65,4.65 4.65,-4.65 -4.65,-4.65
Mechanical 13:
  circle w0.1: c-4.1,4.1 r0.5
  lines w0.1: -5,-5 -5,5 5,5 5,-5 -5,-5
Mechanical 15:
  lines w0.1: -0.5,0 0.5,0 ; 0,-0.5 0,0.5 ; -7.8,-7.8 -7.8,7.8 7.8,7.8 7.8,-7.8 -7.8,-7.8
3D body: height 2.35, standoff 0, extent -5,-5 5,5

## PQ44_N [mm] "44-Pin Plastic Quad Flat Pack (PQ44), IPC Medium Density"
height 2.35
pads (44):
  oval 1.95x0.55 smd: 1(-6.15,4) 2(-6.15,3.2) 3(-6.15,2.4) 4(-6.15,1.6) 5(-6.15,0.8) 6(-6.15,0) 7(-6.15,-0.8) 8(-6.15,-1.6) 9(-6.15,-2.4) 10(-6.15,-3.2) 11(-6.15,-4) 23(6.15,-4) 24(6.15,-3.2) 25(6.15,-2.4) 26(6.15,-1.6) 27(6.15,-0.8) 28(6.15,0) 29(6.15,0.8) 30(6.15,1.6) 31(6.15,2.4) 32(6.15,3.2) 33(6.15,4)
  oval 0.55x1.95 smd: 12(-4,-6.15) 13(-3.2,-6.15) 14(-2.4,-6.15) 15(-1.6,-6.15) 16(-0.8,-6.15) 17(0,-6.15) 18(0.8,-6.15) 19(1.6,-6.15) 20(2.4,-6.15) 21(3.2,-6.15) 22(4,-6.15) 34(4,6.15) 35(3.2,6.15) 36(2.4,6.15) 37(1.6,6.15) 38(0.8,6.15) 39(0,6.15) 40(-0.8,6.15) 41(-1.6,6.15) 42(-2.4,6.15) 43(-3.2,6.15) 44(-4,6.15)
Top Overlay:
  circle w0.6: c-3.75,3.75 r0.3
  circle w0.25: c-6.15,4.825 r0.125
  lines w0.2: -4.75,-4.75 4.75,-4.75 4.75,4.75 -4.75,4.75 -4.75,-4.75
Mechanical 13:
  circle w0.1: c-4.1,4.1 r0.5
  lines w0.1: -5,-5 5,-5 5,5 -5,5 -5,-5
Mechanical 15:
  lines w0.1: -0.5,0 0.5,0 ; 0,-0.5 0,0.5 ; -7.35,-7.35 7.35,-7.35 7.35,7.35 -7.35,7.35 -7.35,-7.35
3D body: height 2.35, standoff 0, extent -5,-5 5,5

## PQ100_L [mm] "100-Pin Plastic Quad Flat Pack (PQ100), IPC High Density"
height 3.4
pads (100):
  oval 1.75x0.45 smd: 1(-8.025,9.425) 2(-8.025,8.775) 3(-8.025,8.125) 4(-8.025,7.475) 5(-8.025,6.825) 6(-8.025,6.175) 7(-8.025,5.525) 8(-8.025,4.875) 9(-8.025,4.225) 10(-8.025,3.575) 11(-8.025,2.925) 12(-8.025,2.275) 13(-8.025,1.625) 14(-8.025,0.975) 15(-8.025,0.325) 16(-8.025,-0.325) 17(-8.025,-0.975) 18(-8.025,-1.625) 19(-8.025,-2.275) 20(-8.025,-2.925) 21(-8.025,-3.575) 22(-8.025,-4.225) 23(-8.025,-4.875) 24(-8.025,-5.525) 25(-8.025,-6.175) 26(-8.025,-6.825) 27(-8.025,-7.475) 28(-8.025,-8.125) 29(-8.025,-8.775) 30(-8.025,-9.425) 51(8.025,-9.425) 52(8.025,-8.775) 53(8.025,-8.125) 54(8.025,-7.475) 55(8.025,-6.825) 56(8.025,-6.175) 57(8.025,-5.525) 58(8.025,-4.875) 59(8.025,-4.225) 60(8.025,-3.575) 61(8.025,-2.925) 62(8.025,-2.275) 63(8.025,-1.625) 64(8.025,-0.975) 65(8.025,-0.325) 66(8.025,0.325) 67(8.025,0.975) 68(8.025,1.625) 69(8.025,2.275) 70(8.025,2.925) 71(8.025,3.575) 72(8.025,4.225) 73(8.025,4.875) 74(8.025,5.525) 75(8.025,6.175) 76(8.025,6.825) 77(8.025,7.475) 78(8.025,8.125) 79(8.025,8.775) 80(8.025,9.425)
  oval 0.45x1.75 smd: 31(-6.175,-11.025) 32(-5.525,-11.025) 33(-4.875,-11.025) 34(-4.225,-11.025) 35(-3.575,-11.025) 36(-2.925,-11.025) 37(-2.275,-11.025) 38(-1.625,-11.025) 39(-0.975,-11.025) 40(-0.325,-11.025) 41(0.325,-11.025) 42(0.975,-11.025) 43(1.625,-11.025) 44(2.275,-11.025) 45(2.925,-11.025) 46(3.575,-11.025) 47(4.225,-11.025) 48(4.875,-11.025) 49(5.525,-11.025) 50(6.175,-11.025) 81(6.175,11.025) 82(5.525,11.025) 83(4.875,11.025) 84(4.225,11.025) 85(3.575,11.025) 86(2.925,11.025) 87(2.275,11.025) 88(1.625,11.025) 89(0.975,11.025) 90(0.325,11.025) 91(-0.325,11.025) 92(-0.975,11.025) 93(-1.625,11.025) 94(-2.275,11.025) 95(-2.925,11.025) 96(-3.575,11.025) 97(-4.225,11.025) 98(-4.875,11.025) 99(-5.525,11.025) 100(-6.175,11.025)
Top Overlay:
  circle w0.6: c-5.75,8.75 r0.3
  circle w0.25: c-8.025,10.2 r0.125
  lines w0.2: -6.75,-9.75 6.75,-9.75 6.75,9.75 -6.75,9.75 -6.75,-9.75
Mechanical 13:
  circle w0.1: c-6.1,9.1 r0.5
  lines w0.1: -7,-10 7,-10 7,10 -7,10 -7,-10
Mechanical 15:
  lines w0.1: -0.5,0 0.5,0 ; 0,-0.5 0,0.5 ; -9,-12 9,-12 9,12 -9,12 -9,-12
3D body: height 3.4, standoff 0, extent -7,-10 7,10

## PQ100_M [mm] "100-Pin Plastic Quad Flat Pack (PQ100), IPC Low Density"
height 3.4
pads (100):
  oval 2.35x0.45 smd: 1(-8.125,9.425) 2(-8.125,8.775) 3(-8.125,8.125) 4(-8.125,7.475) 5(-8.125,6.825) 6(-8.125,6.175) 7(-8.125,5.525) 8(-8.125,4.875) 9(-8.125,4.225) 10(-8.125,3.575) 11(-8.125,2.925) 12(-8.125,2.275) 13(-8.125,1.625) 14(-8.125,0.975) 15(-8.125,0.325) 16(-8.125,-0.325) 17(-8.125,-0.975) 18(-8.125,-1.625) 19(-8.125,-2.275) 20(-8.125,-2.925) 21(-8.125,-3.575) 22(-8.125,-4.225) 23(-8.125,-4.875) 24(-8.125,-5.525) 25(-8.125,-6.175) 26(-8.125,-6.825) 27(-8.125,-7.475) 28(-8.125,-8.125) 29(-8.125,-8.775) 30(-8.125,-9.425) 51(8.125,-9.425) 52(8.125,-8.775) 53(8.125,-8.125) 54(8.125,-7.475) 55(8.125,-6.825) 56(8.125,-6.175) 57(8.125,-5.525) 58(8.125,-4.875) 59(8.125,-4.225) 60(8.125,-3.575) 61(8.125,-2.925) 62(8.125,-2.275) 63(8.125,-1.625) 64(8.125,-0.975) 65(8.125,-0.325) 66(8.125,0.325) 67(8.125,0.975) 68(8.125,1.625) 69(8.125,2.275) 70(8.125,2.925) 71(8.125,3.575) 72(8.125,4.225) 73(8.125,4.875) 74(8.125,5.525) 75(8.125,6.175) 76(8.125,6.825) 77(8.125,7.475) 78(8.125,8.125) 79(8.125,8.775) 80(8.125,9.425)
  oval 0.45x2.35 smd: 31(-6.175,-11.125) 32(-5.525,-11.125) 33(-4.875,-11.125) 34(-4.225,-11.125) 35(-3.575,-11.125) 36(-2.925,-11.125) 37(-2.275,-11.125) 38(-1.625,-11.125) 39(-0.975,-11.125) 40(-0.325,-11.125) 41(0.325,-11.125) 42(0.975,-11.125) 43(1.625,-11.125) 44(2.275,-11.125) 45(2.925,-11.125) 46(3.575,-11.125) 47(4.225,-11.125) 48(4.875,-11.125) 49(5.525,-11.125) 50(6.175,-11.125) 81(6.175,11.125) 82(5.525,11.125) 83(4.875,11.125) 84(4.225,11.125) 85(3.575,11.125) 86(2.925,11.125) 87(2.275,11.125) 88(1.625,11.125) 89(0.975,11.125) 90(0.325,11.125) 91(-0.325,11.125) 92(-0.975,11.125) 93(-1.625,11.125) 94(-2.275,11.125) 95(-2.925,11.125) 96(-3.575,11.125) 97(-4.225,11.125) 98(-4.875,11.125) 99(-5.525,11.125) 100(-6.175,11.125)
Top Overlay:
  circle w0.6: c-5.55,8.55 r0.3
  circle w0.25: c-8.125,10.2 r0.125
  lines w0.2: -6.55,-9.55 6.55,-9.55 6.55,9.55 -6.55,9.55 -6.55,-9.55
Mechanical 13:
  circle w0.1: c-6.1,9.1 r0.5
  lines w0.1: -7,-10 7,-10 7,10 -7,10 -7,-10
Mechanical 15:
  lines w0.1: -0.5,0 0.5,0 ; 0,-0.5 0,0.5 ; -9.8,-12.8 9.8,-12.8 9.8,12.8 -9.8,12.8 -9.8,-12.8
3D body: height 3.4, standoff 0, extent -7,-10 7,10

## PQ100_N [mm] "100-Pin Plastic Quad Flat Pack (PQ100), IPC Medium Density"
height 3.4
pads (100):
  oval 2.05x0.45 smd: 1(-8.075,9.425) 2(-8.075,8.775) 3(-8.075,8.125) 4(-8.075,7.475) 5(-8.075,6.825) 6(-8.075,6.175) 7(-8.075,5.525) 8(-8.075,4.875) 9(-8.075,4.225) 10(-8.075,3.575) 11(-8.075,2.925) 12(-8.075,2.275) 13(-8.075,1.625) 14(-8.075,0.975) 15(-8.075,0.325) 16(-8.075,-0.325) 17(-8.075,-0.975) 18(-8.075,-1.625) 19(-8.075,-2.275) 20(-8.075,-2.925) 21(-8.075,-3.575) 22(-8.075,-4.225) 23(-8.075,-4.875) 24(-8.075,-5.525) 25(-8.075,-6.175) 26(-8.075,-6.825) 27(-8.075,-7.475) 28(-8.075,-8.125) 29(-8.075,-8.775) 30(-8.075,-9.425) 51(8.075,-9.425) 52(8.075,-8.775) 53(8.075,-8.125) 54(8.075,-7.475) 55(8.075,-6.825) 56(8.075,-6.175) 57(8.075,-5.525) 58(8.075,-4.875) 59(8.075,-4.225) 60(8.075,-3.575) 61(8.075,-2.925) 62(8.075,-2.275) 63(8.075,-1.625) 64(8.075,-0.975) 65(8.075,-0.325) 66(8.075,0.325) 67(8.075,0.975) 68(8.075,1.625) 69(8.075,2.275) 70(8.075,2.925) 71(8.075,3.575) 72(8.075,4.225) 73(8.075,4.875) 74(8.075,5.525) 75(8.075,6.175) 76(8.075,6.825) 77(8.075,7.475) 78(8.075,8.125) 79(8.075,8.775) 80(8.075,9.425)
  oval 0.45x2.05 smd: 31(-6.175,-11.075) 32(-5.525,-11.075) 33(-4.875,-11.075) 34(-4.225,-11.075) 35(-3.575,-11.075) 36(-2.925,-11.075) 37(-2.275,-11.075) 38(-1.625,-11.075) 39(-0.975,-11.075) 40(-0.325,-11.075) 41(0.325,-11.075) 42(0.975,-11.075) 43(1.625,-11.075) 44(2.275,-11.075) 45(2.925,-11.075) 46(3.575,-11.075) 47(4.225,-11.075) 48(4.875,-11.075) 49(5.525,-11.075) 50(6.175,-11.075) 81(6.175,11.075) 82(5.525,11.075) 83(4.875,11.075) 84(4.225,11.075) 85(3.575,11.075) 86(2.925,11.075) 87(2.275,11.075) 88(1.625,11.075) 89(0.975,11.075) 90(0.325,11.075) 91(-0.325,11.075) 92(-0.975,11.075) 93(-1.625,11.075) 94(-2.275,11.075) 95(-2.925,11.075) 96(-3.575,11.075) 97(-4.225,11.075) 98(-4.875,11.075) 99(-5.525,11.075) 100(-6.175,11.075)
Top Overlay:
  circle w0.25: c-8.075,10.2 r0.125
  circle w0.6: c-5.65,8.65 r0.3
  lines w0.2: -6.65,-9.65 -6.65,9.65 6.65,9.65 6.65,-9.65 -6.65,-9.65
Mechanical 13:
  circle w0.1: c-6.1,9.1 r0.5
  lines w0.1: -7,-10 -7,10 7,10 7,-10 -7,-10
Mechanical 15:
  lines w0.1: -0.5,0 0.5,0 ; 0,-0.5 0,0.5 ; -9.35,-12.35 -9.35,12.35 9.35,12.35 9.35,-12.35 -9.35,-12.35
3D body: height 3.4, standoff 0, extent -7,-10 7,10

## PQ160_L [mm] "160-Pin Plastic Quad Flat Pack (PQ160), IPC High Density"
height 4.1
pads (160):
  oval 1.65x0.45 smd: 1(-15.1,12.675) 2(-15.1,12.025) 3(-15.1,11.375) 4(-15.1,10.725) 5(-15.1,10.075) 6(-15.1,9.425) 7(-15.1,8.775) 8(-15.1,8.125) 9(-15.1,7.475) 10(-15.1,6.825) 11(-15.1,6.175) 12(-15.1,5.525) 13(-15.1,4.875) 14(-15.1,4.225) 15(-15.1,3.575) 16(-15.1,2.925) 17(-15.1,2.275) 18(-15.1,1.625) 19(-15.1,0.975) 20(-15.1,0.325) 21(-15.1,-0.325) 22(-15.1,-0.975) 23(-15.1,-1.625) 24(-15.1,-2.275) 25(-15.1,-2.925) 26(-15.1,-3.575) 27(-15.1,-4.225) 28(-15.1,-4.875) 29(-15.1,-5.525) 30(-15.1,-6.175) 31(-15.1,-6.825) 32(-15.1,-7.475) 33(-15.1,-8.125) 34(-15.1,-8.775) 35(-15.1,-9.425) 36(-15.1,-10.075) 37(-15.1,-10.725) 38(-15.1,-11.375) 39(-15.1,-12.025) 40(-15.1,-12.675) 81(15.1,-12.675) 82(15.1,-12.025) 83(15.1,-11.375) 84(15.1,-10.725) 85(15.1,-10.075) 86(15.1,-9.425) 87(15.1,-8.775) 88(15.1,-8.125) 89(15.1,-7.475) 90(15.1,-6.825) 91(15.1,-6.175) 92(15.1,-5.525) 93(15.1,-4.875) 94(15.1,-4.225) 95(15.1,-3.575) 96(15.1,-2.925) 97(15.1,-2.275) 98(15.1,-1.625) 99(15.1,-0.975) 100(15.1,-0.325) 101(15.1,0.325) 102(15.1,0.975) 103(15.1,1.625) 104(15.1,2.275) 105(15.1,2.925) 106(15.1,3.575) 107(15.1,4.225) 108(15.1,4.875) 109(15.1,5.525) 110(15.1,6.175) 111(15.1,6.825) 112(15.1,7.475) 113(15.1,8.125) 114(15.1,8.775) 115(15.1,9.425) 116(15.1,10.075) 117(15.1,10.725) 118(15.1,11.375) 119(15.1,12.025) 120(15.1,12.675)
  oval 0.45x1.65 smd: 41(-12.675,-15.1) 42(-12.025,-15.1) 43(-11.375,-15.1) 44(-10.725,-15.1) 45(-10.075,-15.1) 46(-9.425,-15.1) 47(-8.775,-15.1) 48(-8.125,-15.1) 49(-7.475,-15.1) 50(-6.825,-15.1) 51(-6.175,-15.1) 52(-5.525,-15.1) 53(-4.875,-15.1) 54(-4.225,-15.1) 55(-3.575,-15.1) 56(-2.925,-15.1) 57(-2.275,-15.1) 58(-1.625,-15.1) 59(-0.975,-15.1) 60(-0.325,-15.1) 61(0.325,-15.1) 62(0.975,-15.1) 63(1.625,-15.1) 64(2.275,-15.1) 65(2.925,-15.1) 66(3.575,-15.1) 67(4.225,-15.1) 68(4.875,-15.1) 69(5.525,-15.1) 70(6.175,-15.1) 71(6.825,-15.1) 72(7.475,-15.1) 73(8.125,-15.1) 74(8.775,-15.1) 75(9.425,-15.1) 76(10.075,-15.1) 77(10.725,-15.1) 78(11.375,-15.1) 79(12.025,-15.1) 80(12.675,-15.1) 121(12.675,15.1) 122(12.025,15.1) 123(11.375,15.1) 124(10.725,15.1) 125(10.075,15.1) 126(9.425,15.1) 127(8.775,15.1) 128(8.125,15.1) 129(7.475,15.1) 130(6.825,15.1) 131(6.175,15.1) 132(5.525,15.1) 133(4.875,15.1) 134(4.225,15.1) 135(3.575,15.1) 136(2.925,15.1) 137(2.275,15.1) 138(1.625,15.1) 139(0.975,15.1) 140(0.325,15.1) 141(-0.325,15.1) 142(-0.975,15.1) 143(-1.625,15.1) 144(-2.275,15.1) 145(-2.925,15.1) 146(-3.575,15.1) 147(-4.225,15.1) 148(-4.875,15.1) 149(-5.525,15.1) 150(-6.175,15.1) 151(-6.825,15.1) 152(-7.475,15.1) 153(-8.125,15.1) 154(-8.775,15.1) 155(-9.425,15.1) 156(-10.075,15.1) 157(-10.725,15.1) 158(-11.375,15.1) 159(-12.025,15.1) 160(-12.675,15.1)
Top Overlay:
  circle w0.25: c-15.1,13.45 r0.125
  circle w0.6: c-12.85,12.85 r0.3
  lines w0.2: -13.85,-13.85 -13.85,13.85 13.85,13.85 13.85,-13.85 -13.85,-13.85
Mechanical 13:
  circle w0.1: c-13.1,13.1 r0.5
  lines w0.1: -14,-14 -14,14 14,14 14,-14 -14,-14
Mechanical 15:
  lines w0.1: -0.5,0 0.5,0 ; 0,-0.5 0,0.5 ; -16,-16 -16,16 16,16 16,-16 -16,-16
3D body: height 4.1, standoff 0, extent -14,-14 14,14

## PQ160_M [mm] "160-Pin Plastic Quad Flat Pack (PQ160), IPC Low Density"
height 4.1
pads (160):
  oval 2.25x0.45 smd: 1(-15.2,12.675) 2(-15.2,12.025) 3(-15.2,11.375) 4(-15.2,10.725) 5(-15.2,10.075) 6(-15.2,9.425) 7(-15.2,8.775) 8(-15.2,8.125) 9(-15.2,7.475) 10(-15.2,6.825) 11(-15.2,6.175) 12(-15.2,5.525) 13(-15.2,4.875) 14(-15.2,4.225) 15(-15.2,3.575) 16(-15.2,2.925) 17(-15.2,2.275) 18(-15.2,1.625) 19(-15.2,0.975) 20(-15.2,0.325) 21(-15.2,-0.325) 22(-15.2,-0.975) 23(-15.2,-1.625) 24(-15.2,-2.275) 25(-15.2,-2.925) 26(-15.2,-3.575) 27(-15.2,-4.225) 28(-15.2,-4.875) 29(-15.2,-5.525) 30(-15.2,-6.175) 31(-15.2,-6.825) 32(-15.2,-7.475) 33(-15.2,-8.125) 34(-15.2,-8.775) 35(-15.2,-9.425) 36(-15.2,-10.075) 37(-15.2,-10.725) 38(-15.2,-11.375) 39(-15.2,-12.025) 40(-15.2,-12.675) 81(15.2,-12.675) 82(15.2,-12.025) 83(15.2,-11.375) 84(15.2,-10.725) 85(15.2,-10.075) 86(15.2,-9.425) 87(15.2,-8.775) 88(15.2,-8.125) 89(15.2,-7.475) 90(15.2,-6.825) 91(15.2,-6.175) 92(15.2,-5.525) 93(15.2,-4.875) 94(15.2,-4.225) 95(15.2,-3.575) 96(15.2,-2.925) 97(15.2,-2.275) 98(15.2,-1.625) 99(15.2,-0.975) 100(15.2,-0.325) 101(15.2,0.325) 102(15.2,0.975) 103(15.2,1.625) 104(15.2,2.275) 105(15.2,2.925) 106(15.2,3.575) 107(15.2,4.225) 108(15.2,4.875) 109(15.2,5.525) 110(15.2,6.175) 111(15.2,6.825) 112(15.2,7.475) 113(15.2,8.125) 114(15.2,8.775) 115(15.2,9.425) 116(15.2,10.075) 117(15.2,10.725) 118(15.2,11.375) 119(15.2,12.025) 120(15.2,12.675)
  oval 0.45x2.25 smd: 41(-12.675,-15.2) 42(-12.025,-15.2) 43(-11.375,-15.2) 44(-10.725,-15.2) 45(-10.075,-15.2) 46(-9.425,-15.2) 47(-8.775,-15.2) 48(-8.125,-15.2) 49(-7.475,-15.2) 50(-6.825,-15.2) 51(-6.175,-15.2) 52(-5.525,-15.2) 53(-4.875,-15.2) 54(-4.225,-15.2) 55(-3.575,-15.2) 56(-2.925,-15.2) 57(-2.275,-15.2) 58(-1.625,-15.2) 59(-0.975,-15.2) 60(-0.325,-15.2) 61(0.325,-15.2) 62(0.975,-15.2) 63(1.625,-15.2) 64(2.275,-15.2) 65(2.925,-15.2) 66(3.575,-15.2) 67(4.225,-15.2) 68(4.875,-15.2) 69(5.525,-15.2) 70(6.175,-15.2) 71(6.825,-15.2) 72(7.475,-15.2) 73(8.125,-15.2) 74(8.775,-15.2) 75(9.425,-15.2) 76(10.075,-15.2) 77(10.725,-15.2) 78(11.375,-15.2) 79(12.025,-15.2) 80(12.675,-15.2) 121(12.675,15.2) 122(12.025,15.2) 123(11.375,15.2) 124(10.725,15.2) 125(10.075,15.2) 126(9.425,15.2) 127(8.775,15.2) 128(8.125,15.2) 129(7.475,15.2) 130(6.825,15.2) 131(6.175,15.2) 132(5.525,15.2) 133(4.875,15.2) 134(4.225,15.2) 135(3.575,15.2) 136(2.925,15.2) 137(2.275,15.2) 138(1.625,15.2) 139(0.975,15.2) 140(0.325,15.2) 141(-0.325,15.2) 142(-0.975,15.2) 143(-1.625,15.2) 144(-2.275,15.2) 145(-2.925,15.2) 146(-3.575,15.2) 147(-4.225,15.2) 148(-4.875,15.2) 149(-5.525,15.2) 150(-6.175,15.2) 151(-6.825,15.2) 152(-7.475,15.2) 153(-8.125,15.2) 154(-8.775,15.2) 155(-9.425,15.2) 156(-10.075,15.2) 157(-10.725,15.2) 158(-11.375,15.2) 159(-12.025,15.2) 160(-12.675,15.2)
Top Overlay:
  circle w0.6: c-12.65,12.65 r0.3
  circle w0.25: c-15.2,13.45 r0.125
  lines w0.2: -13.65,-13.65 13.65,-13.65 13.65,13.65 -13.65,13.65 -13.65,-13.65
Mechanical 13:
  circle w0.1: c-13.1,13.1 r0.5
  lines w0.1: -14,-14 14,-14 14,14 -14,14 -14,-14
Mechanical 15:
  lines w0.1: -0.5,0 0.5,0 ; 0,-0.5 0,0.5 ; -16.8,-16.8 16.8,-16.8 16.8,16.8 -16.8,16.8 -16.8,-16.8
3D body: height 4.1, standoff 0, extent -14,-14 14,14

## PQ160_N [mm] "160-Pin Plastic Quad Flat Pack (PQ160), IPC Medium Density"
height 4.1
pads (160):
  oval 1.95x0.45 smd: 1(-15.15,12.675) 2(-15.15,12.025) 3(-15.15,11.375) 4(-15.15,10.725) 5(-15.15,10.075) 6(-15.15,9.425) 7(-15.15,8.775) 8(-15.15,8.125) 9(-15.15,7.475) 10(-15.15,6.825) 11(-15.15,6.175) 12(-15.15,5.525) 13(-15.15,4.875) 14(-15.15,4.225) 15(-15.15,3.575) 16(-15.15,2.925) 17(-15.15,2.275) 18(-15.15,1.625) 19(-15.15,0.975) 20(-15.15,0.325) 21(-15.15,-0.325) 22(-15.15,-0.975) 23(-15.15,-1.625) 24(-15.15,-2.275) 25(-15.15,-2.925) 26(-15.15,-3.575) 27(-15.15,-4.225) 28(-15.15,-4.875) 29(-15.15,-5.525) 30(-15.15,-6.175) 31(-15.15,-6.825) 32(-15.15,-7.475) 33(-15.15,-8.125) 34(-15.15,-8.775) 35(-15.15,-9.425) 36(-15.15,-10.075) 37(-15.15,-10.725) 38(-15.15,-11.375) 39(-15.15,-12.025) 40(-15.15,-12.675) 81(15.15,-12.675) 82(15.15,-12.025) 83(15.15,-11.375) 84(15.15,-10.725) 85(15.15,-10.075) 86(15.15,-9.425) 87(15.15,-8.775) 88(15.15,-8.125) 89(15.15,-7.475) 90(15.15,-6.825) 91(15.15,-6.175) 92(15.15,-5.525) 93(15.15,-4.875) 94(15.15,-4.225) 95(15.15,-3.575) 96(15.15,-2.925) 97(15.15,-2.275) 98(15.15,-1.625) 99(15.15,-0.975) 100(15.15,-0.325) 101(15.15,0.325) 102(15.15,0.975) 103(15.15,1.625) 104(15.15,2.275) 105(15.15,2.925) 106(15.15,3.575) 107(15.15,4.225) 108(15.15,4.875) 109(15.15,5.525) 110(15.15,6.175) 111(15.15,6.825) 112(15.15,7.475) 113(15.15,8.125) 114(15.15,8.775) 115(15.15,9.425) 116(15.15,10.075) 117(15.15,10.725) 118(15.15,11.375) 119(15.15,12.025) 120(15.15,12.675)
  oval 0.45x1.95 smd: 41(-12.675,-15.15) 42(-12.025,-15.15) 43(-11.375,-15.15) 44(-10.725,-15.15) 45(-10.075,-15.15) 46(-9.425,-15.15) 47(-8.775,-15.15) 48(-8.125,-15.15) 49(-7.475,-15.15) 50(-6.825,-15.15) 51(-6.175,-15.15) 52(-5.525,-15.15) 53(-4.875,-15.15) 54(-4.225,-15.15) 55(-3.575,-15.15) 56(-2.925,-15.15) 57(-2.275,-15.15) 58(-1.625,-15.15) 59(-0.975,-15.15) 60(-0.325,-15.15) 61(0.325,-15.15) 62(0.975,-15.15) 63(1.625,-15.15) 64(2.275,-15.15) 65(2.925,-15.15) 66(3.575,-15.15) 67(4.225,-15.15) 68(4.875,-15.15) 69(5.525,-15.15) 70(6.175,-15.15) 71(6.825,-15.15) 72(7.475,-15.15) 73(8.125,-15.15) 74(8.775,-15.15) 75(9.425,-15.15) 76(10.075,-15.15) 77(10.725,-15.15) 78(11.375,-15.15) 79(12.025,-15.15) 80(12.675,-15.15) 121(12.675,15.15) 122(12.025,15.15) 123(11.375,15.15) 124(10.725,15.15) 125(10.075,15.15) 126(9.425,15.15) 127(8.775,15.15) 128(8.125,15.15) 129(7.475,15.15) 130(6.825,15.15) 131(6.175,15.15) 132(5.525,15.15) 133(4.875,15.15) 134(4.225,15.15) 135(3.575,15.15) 136(2.925,15.15) 137(2.275,15.15) 138(1.625,15.15) 139(0.975,15.15) 140(0.325,15.15) 141(-0.325,15.15) 142(-0.975,15.15) 143(-1.625,15.15) 144(-2.275,15.15) 145(-2.925,15.15) 146(-3.575,15.15) 147(-4.225,15.15) 148(-4.875,15.15) 149(-5.525,15.15) 150(-6.175,15.15) 151(-6.825,15.15) 152(-7.475,15.15) 153(-8.125,15.15) 154(-8.775,15.15) 155(-9.425,15.15) 156(-10.075,15.15) 157(-10.725,15.15) 158(-11.375,15.15) 159(-12.025,15.15) 160(-12.675,15.15)
Top Overlay:
  circle w0.6: c-12.75,12.75 r0.3
  circle w0.25: c-15.15,13.45 r0.125
  lines w0.2: -13.75,-13.75 13.75,-13.75 13.75,13.75 -13.75,13.75 -13.75,-13.75
Mechanical 13:
  circle w0.1: c-13.1,13.1 r0.5
  lines w0.1: -14,-14 14,-14 14,14 -14,14 -14,-14
Mechanical 15:
  lines w0.1: -0.5,0 0.5,0 ; 0,-0.5 0,0.5 ; -16.35,-16.35 16.35,-16.35 16.35,16.35 -16.35,16.35 -16.35,-16.35
3D body: height 4.1, standoff 0, extent -14,-14 14,14

## PQ208_L [mm] "208-Pin Plastic Quad Flat Pack (PQ208), IPC High Density"
height 4.1
pads (208):
  oval 1.55x0.25 smd: 1(-14.825,12.75) 2(-14.825,12.25) 3(-14.825,11.75) 4(-14.825,11.25) 5(-14.825,10.75) 6(-14.825,10.25) 7(-14.825,9.75) 8(-14.825,9.25) 9(-14.825,8.75) 10(-14.825,8.25) 11(-14.825,7.75) 12(-14.825,7.25) 13(-14.825,6.75) 14(-14.825,6.25) 15(-14.825,5.75) 16(-14.825,5.25) 17(-14.825,4.75) 18(-14.825,4.25) 19(-14.825,3.75) 20(-14.825,3.25) 21(-14.825,2.75) 22(-14.825,2.25) 23(-14.825,1.75) 24(-14.825,1.25) 25(-14.825,0.75) 26(-14.825,0.25) 27(-14.825,-0.25) 28(-14.825,-0.75) 29(-14.825,-1.25) 30(-14.825,-1.75) 31(-14.825,-2.25) 32(-14.825,-2.75) 33(-14.825,-3.25) 34(-14.825,-3.75) 35(-14.825,-4.25) 36(-14.825,-4.75) 37(-14.825,-5.25) 38(-14.825,-5.75) 39(-14.825,-6.25) 40(-14.825,-6.75) 41(-14.825,-7.25) 42(-14.825,-7.75) 43(-14.825,-8.25) 44(-14.825,-8.75) 45(-14.825,-9.25) 46(-14.825,-9.75) 47(-14.825,-10.25) 48(-14.825,-10.75) 49(-14.825,-11.25) 50(-14.825,-11.75) 51(-14.825,-12.25) 52(-14.825,-12.75) 105(14.825,-12.75) 106(14.825,-12.25) 107(14.825,-11.75) 108(14.825,-11.25) 109(14.825,-10.75) 110(14.825,-10.25) 111(14.825,-9.75) 112(14.825,-9.25) 113(14.825,-8.75) 114(14.825,-8.25) 115(14.825,-7.75) 116(14.825,-7.25) 117(14.825,-6.75) 118(14.825,-6.25) 119(14.825,-5.75) 120(14.825,-5.25) 121(14.825,-4.75) 122(14.825,-4.25) 123(14.825,-3.75) 124(14.825,-3.25) 125(14.825,-2.75) 126(14.825,-2.25) 127(14.825,-1.75) 128(14.825,-1.25) 129(14.825,-0.75) 130(14.825,-0.25) 131(14.825,0.25) 132(14.825,0.75) 133(14.825,1.25) 134(14.825,1.75) 135(14.825,2.25) 136(14.825,2.75) 137(14.825,3.25) 138(14.825,3.75) 139(14.825,4.25) 140(14.825,4.75) 141(14.825,5.25) 142(14.825,5.75) 143(14.825,6.25) 144(14.825,6.75) 145(14.825,7.25) 146(14.825,7.75) 147(14.825,8.25) 148(14.825,8.75) 149(14.825,9.25) 150(14.825,9.75) 151(14.825,10.25) 152(14.825,10.75) 153(14.825,11.25) 154(14.825,11.75) 155(14.825,12.25) 156(14.825,12.75)
  oval 0.25x1.55 smd: 53(-12.75,-14.825) 54(-12.25,-14.825) 55(-11.75,-14.825) 56(-11.25,-14.825) 57(-10.75,-14.825) 58(-10.25,-14.825) 59(-9.75,-14.825) 60(-9.25,-14.825) 61(-8.75,-14.825) 62(-8.25,-14.825) 63(-7.75,-14.825) 64(-7.25,-14.825) 65(-6.75,-14.825) 66(-6.25,-14.825) 67(-5.75,-14.825) 68(-5.25,-14.825) 69(-4.75,-14.825) 70(-4.25,-14.825) 71(-3.75,-14.825) 72(-3.25,-14.825) 73(-2.75,-14.825) 74(-2.25,-14.825) 75(-1.75,-14.825) 76(-1.25,-14.825) 77(-0.75,-14.825) 78(-0.25,-14.825) 79(0.25,-14.825) 80(0.75,-14.825) 81(1.25,-14.825) 82(1.75,-14.825) 83(2.25,-14.825) 84(2.75,-14.825) 85(3.25,-14.825) 86(3.75,-14.825) 87(4.25,-14.825) 88(4.75,-14.825) 89(5.25,-14.825) 90(5.75,-14.825) 91(6.25,-14.825) 92(6.75,-14.825) 93(7.25,-14.825) 94(7.75,-14.825) 95(8.25,-14.825) 96(8.75,-14.825) 97(9.25,-14.825) 98(9.75,-14.825) 99(10.25,-14.825) 100(10.75,-14.825) 101(11.25,-14.825) 102(11.75,-14.825) 103(12.25,-14.825) 104(12.75,-14.825) 157(12.75,14.825) 158(12.25,14.825) 159(11.75,14.825) 160(11.25,14.825) 161(10.75,14.825) 162(10.25,14.825) 163(9.75,14.825) 164(9.25,14.825) 165(8.75,14.825) 166(8.25,14.825) 167(7.75,14.825) 168(7.25,14.825) 169(6.75,14.825) 170(6.25,14.825) 171(5.75,14.825) 172(5.25,14.825) 173(4.75,14.825) 174(4.25,14.825) 175(3.75,14.825) 176(3.25,14.825) 177(2.75,14.825) 178(2.25,14.825) 179(1.75,14.825) 180(1.25,14.825) 181(0.75,14.825) 182(0.25,14.825) 183(-0.25,14.825) 184(-0.75,14.825) 185(-1.25,14.825) 186(-1.75,14.825) 187(-2.25,14.825) 188(-2.75,14.825) 189(-3.25,14.825) 190(-3.75,14.825) 191(-4.25,14.825) 192(-4.75,14.825) 193(-5.25,14.825) 194(-5.75,14.825) 195(-6.25,14.825) 196(-6.75,14.825) 197(-7.25,14.825) 198(-7.75,14.825) 199(-8.25,14.825) 200(-8.75,14.825) 201(-9.25,14.825) 202(-9.75,14.825) 203(-10.25,14.825) 204(-10.75,14.825) 205(-11.25,14.825) 206(-11.75,14.825) 207(-12.25,14.825) 208(-12.75,14.825)
Top Overlay:
  circle w0.6: c-12.65,12.65 r0.3
  circle w0.25: c-14.825,13.425 r0.125
  lines w0.2: -13.65,-13.65 13.65,-13.65 13.65,13.65 -13.65,13.65 -13.65,-13.65
Mechanical 13:
  circle w0.1: c-13.1,13.1 r0.5
  lines w0.1: -14,-14 14,-14 14,14 -14,14 -14,-14
Mechanical 15:
  lines w0.1: -0.5,0 0.5,0 ; 0,-0.5 0,0.5 ; -15.7,-15.7 15.7,-15.7 15.7,15.7 -15.7,15.7 -15.7,-15.7
3D body: height 4.1, standoff 0, extent -14,-14 14,14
